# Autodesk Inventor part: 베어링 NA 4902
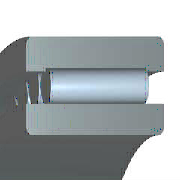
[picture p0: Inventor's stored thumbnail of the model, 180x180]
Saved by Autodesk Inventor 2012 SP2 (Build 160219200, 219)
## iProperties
IsCustomPart: 0
Manager: KYOUNG IL JANG
Company: 한국ATC센터
Created: 2009-02
Part Number: 베어링 NA 4902
Material: Steel, Mild
Description: 니들 롤러 베어링 - 경계 치수 및 공차
Document SubType Name: Modeling
Standard: KS B 2029
Standards Organization: KS
Language: ko-KR
Size Designation: NA 4902 - 15 x 28 x 13
Categories: <MemberInstance><Categories><Category DisplayName="샤프트 부품" InternalName="7f7aeb1f-a693-4053-b835-cee3144e0d98" Mnemonic="SHFT"><Category DisplayName="베어링" Inter
Density: 1 g/cm^3
Checked By: KYOUNG IL JANG
Vendor: CBT Solutions
Designer: KYOUNG IL JANG
Author: KYOUNG IL JANG
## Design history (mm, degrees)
revolve "본체" stored, may be unused: angle "d17" = 90 deg
revolve "롤러" stored, may be unused: angle "d18" = 90 deg
body "Solid1"
sketch "스케치"
  geometry: L1 (1.857, 11.5)-(11.143, 11.5); L2 (11.143, 11.5)-(11.143, 10); L3 (13, 10)-(0, 10); L4 (1.857, 10)-(1.857, 11.5); L5 (1.857, 10.75)-(11.143, 10.75); L6 (6.5, 10.75)-(6.5, 10); L7 (0, 7.5)-(13, 7.5); L8 (0, 14)-(13, 14); L9 (13, 7.5)-(13, 10); L10 (13, 11.35)-(13, 14); L11 (1.857, 11.35)-(0, 11.35); L12 (11.143, 11.35)-(13, 11.35); L13 (-6, 0)-(36, 0) reference; L14 (0, -1.9)-(0, 14.9) reference
  constraints: 24 end point, 8 point on line, 3 midpoint, 3 parallel, 3 perpendicular, 2 symmetric about line, 1 horizontal, 1 other
  dimensions: "d6" = 15 diameter of L7 L13 (= WD); "d7" = 20 diameter of L3 L13 (= KID1); "d8" = 28 diameter of L8 L13 (= BD); "d9" = 21.5 diameter of L6.start L13 (= 0.5 x WD + 0.5 x BD); "d10" = 22.7 diameter of L12 L13 (= 0.9 x BD + 0.9 x WD - 0.8 x KID1); "d11" = 23 diameter of L1 L13 (= BD + WD - KID1); "d12" = 1.85714 distance between parallel lines of L14 L4 (= 0.142857 x KB); "d13" = 13 distance between parallel lines of L14 L9 (= KB); "d14" = 11.14286 distance between parallel lines of L14 L2 (= 0.857143 x KB)
fillet "모깎기1" dims "d0" = 0.3 (= KRS)
pattern_circular "IDS_ARRAYROLLER[SIMPL:T]" dims angle "d2" = 360 deg
other parameters: "WD" = 15 [user parameter; used in 6 equation terms], "BD" = 28 [user parameter; used in 6 equation terms], "KB" = 13 [user parameter; used in 3 equation terms], "KID1" = 20 [user parameter; used in 4 equation terms], "KRS" = 0.3 [user parameter; used in 1 equation term], "d3" = 0, "d4" = 0, "d5" = 0, "d15" = 0, "d16" = 0, "BC0" = 1.37e+07 [user parameter], "WR" = 7.5 (= 0.5 x WD) [user parameter], "BBA" = 0 [user parameter], "BC" = 1.02e+07 [user parameter], "BR" = 14 (= 0.5 x BD) [user parameter]
